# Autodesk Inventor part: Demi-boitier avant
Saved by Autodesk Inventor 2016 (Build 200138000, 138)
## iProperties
Created: 2013-08
Part Number: Demi-boitier avant
Material: Générique
Document SubType Name: Modeling
Designer: hilarion
Density: 1 g/cm^3
Appearance: Par défaut
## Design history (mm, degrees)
node "Demi-boitier avant1"
node "Demi-boitier avant"
node "Base1"
